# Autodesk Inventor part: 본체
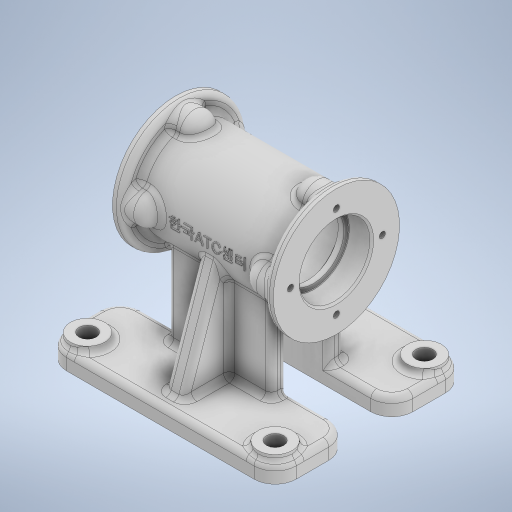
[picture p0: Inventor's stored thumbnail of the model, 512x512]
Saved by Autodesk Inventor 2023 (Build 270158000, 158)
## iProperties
Created: 2026-06
Part Number: 본체
Material: 일반
Document SubType Name: Modeling
Designer: 4강의실
Density: 1 g/cm^3
Appearance: 기본값
Author: 4강의실
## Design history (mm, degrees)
sketch "스케치1"
  geometry: L1 (-42, 0)-(-42, 33); L2 (-42, 33)-(-37, 33); L3 (-37, 33)-(-37, 25); L4 (-37, 25)-(37, 25); L5 (37, 25)-(37, 33); L6 (37, 33)-(42, 33); L7 (42, 33)-(42, 0); L8 (42, 0)-(-42, 0); 2 further points
  constraints: 16 end point, 5 perpendicular, 2 point on line, 1 coincident, 1 collinear, 1 horizontal, 1 midpoint, 1 vertical
  dimensions: "d0" = 84 distance between parallel lines of L7 L1; "d1" = 66 diameter of L2 L8; "d2" = 50 diameter of L4 L8; "d3" = 5 distance of L5.end L6.end
revolve "회전1" sketch "스케치1" stored, may be unused: angle "d4" = 90 deg
sketch "스케치3"
  geometry: L1 (-61, -50)-(-70, -50); L2 (-70, -50)-(-70, -11); L3 (-70, -11)-(-61, -11); L4 (-61, -11)-(-61, -50); L5 (0, 0)-(-63.878, 0); L6 (-61, -11)-(-22.45, -11); L7 (-16.248, -19)-(-61, -19); C1 r 33 at (0, 0) reference; A1 r 25 centre (0, 0) between (-22.45, -11) and (-16.248, -19) reference
  constraints: 14 end point, 3 horizontal, 2 parallel, 2 perpendicular, 2 point on circle, 1 point on line
  dimensions: "d12" = 70 distance from line of L2 L5.start; "d13" = 9 distance of L2.end L3.end; "d14" = 39 distance of L1.end L2.end; "d15" = 100 diameter of L1 L5; "d19" = 8 distance between parallel lines of L6 L7
extrude "돌출1" join sketch "스케치3" stored distance "d17" = 120; taper "d18" = 0 deg
extrude "돌출2" join sketch "스케치3" stored distance "d20" = 54; taper "d21" = 0 deg
sketch "스케치4"
  geometry: L1 (-6.346, -24.181)-(-61, -43); L2 (-61, -50)-(-61, -11) reference; L3 (-61, -19)-(-16.248, -19) reference; L4 (-70, -50)-(-61, -50) reference; A1 r 25 centre (0, 0) between (-6.346, -24.181) and (-16.248, -19) reference; 1 further point
  constraints: 2 end point, 1 point on circle, 1 point on line
  dimensions: "d22" = 19 deg angle of L3 L1; "d23" = 7 distance from line of L1.end L4
feature "리브1" sketch "스케치4" dims "d24" = 1, "d25" = 10, "d26" = 0, "d27" = 0, "d28" = 1, "d29" = 1
sketch "스케치5"
  geometry: L1 (0, 0)-(120, 0) reference; L2 (60, 0)-(60, 15.652); L3 (18, -17)-(18, -83) reference; L4 (18, -50)-(3.294, -50); C1 r 9 at (109, -11); C2 r 9 at (11, -11); 1 further point
  constraints: 4 end point, 2 centre point, 2 midpoint, 1 horizontal, 1 symmetric about line, 1 vertical, 1 other
  dimensions: "d30" = 18 diameter of C1; "d31" = 98 diameter of C1.centre L2; "d32" = 78 diameter of C1.centre L4
extrude "돌출3" join sketch "스케치5" distance "d33" = 3; taper "d34" = 0 deg
fillet "모깎기3" dims "d75" = 3
sketch "스케치6"
  geometry: L1 (42, 33)-(42, -33) reference; L2 (32, 32)-(37, 32); L3 (37, 33)-(37, -33) reference; L4 (32, 24)-(24, 24); L5 (37, 25)-(37, -25) reference; L6 (37, 32)-(37, 25); L7 (37, 25)-(24.063, 25); L8 (37, 25)-(-37, 25) reference; A1 r 8 centre (32, 24) between (37, 30.245) and (37, 17.755); A2 r 8 centre (32, 24) between (37, 17.755) and (37, 30.245); 1 further point
  constraints: 8 end point, 7 point on circle, 4 point on line, 2 centre point, 1 horizontal, 1 tangent
  dimensions: "d35" = 16 diameter of A1; "d36" = 24 vertical distance of point (0, 0) L4.start; "d37" = 10 distance from line of L1 L4.start
revolve "회전3" sketch "스케치6" stored, may be unused: angle "d38" = 90 deg
sketch "스케치8"
  geometry: 6 further points
  constraints: 2 vertical alignment, 1 coincident, 7 other
  dimensions: "d48" = 24 distance of point (0, 24) point (0, 0); "d51" = 360 deg dimension on point (0, 0) point (0, 24) (derived)
hole "구멍1" sketch "스케치8" at (0, 24), (-24, 0), (0, -24), (24, 0) diameter "d53" = 3.242; stored, may be unused: countersink angle "d57" = 90 deg, drill point angle "d59" = 118 deg; dims "d54" = 8, "d55" = 4, "d56" = 2, "d58" = 10
sketch "스케치7"
  geometry: L1 (42, 33)-(42, -33) reference; L2 (42, 0)-(30, 0); L3 (30, 0)-(30, 18.5); L4 (30, 18.5)-(42, 18.5); L5 (42, 18.5)-(42, 0); L6 (30, 0)-(27, 0); L7 (27, 0)-(27, 16); L8 (27, 16)-(30, 16); L9 (30, 16)-(30, 0); L10 (27, 0)-(-27, 0); L11 (-27, 0)-(-27, 20); L12 (-27, 20)-(27, 20); L13 (27, 20)-(27, 0); L14 (-27, 0)-(-30, 0); L15 (-30, 0)-(-30, 16); L16 (-30, 16)-(-27, 16); L17 (-27, 16)-(-27, 0); L18 (-42, 33)-(-42, -33) reference; L19 (-30, 0)-(-42, 0); L20 (-42, 0)-(-42, 18.5); L21 (-42, 18.5)-(-30, 18.5); L22 (-30, 18.5)-(-30, 0); 7 further points
  constraints: 40 end point, 10 parallel, 5 horizontal, 5 perpendicular, 3 point on line, 2 collinear, 1 midpoint
  dimensions: "d42" = 37 diameter of L4 L2; "d43" = 12 distance between parallel lines of L3 L5; "d44" = 54 distance of L11.end L12.end; "d45" = 40 diameter of L12 L10; "d46" = 32 diameter of L8 L6
revolve "회전4" sketch "스케치7" stored, may be unused: angle "d47" = 90 deg
sketch "스케치9"
  geometry: C1 r 9 at (0, 0) reference; C2 r 9 at (-98, 0) reference; C3 r 9 at (-98, -78) reference; C4 r 9 at (0, -78) reference; 5 further points
  constraints: 4 coincident
hole "구멍2" sketch "스케치9" at (0, 0), (-98, 0), (-98, -78), (0, -78) diameter "d60" = 9; stored, may be unused: countersink angle "d64" = 90 deg, drill point angle "d66" = 118 deg; dims "d61" = 8, "d62" = 4, "d63" = 2, "d65" = 10
chamfer "모따기1" distance "d67" = 1; stored, may be unused: second distance "d68" = 2, angle "d69" = 45 deg
fillet "모깎기6" dims "d78" = 11
fillet "모깎기1" dims "d73" = 0.3
fillet "모깎기2" dims "d74" = 3
fillet "모깎기4" dims "d76" = 3
fillet "모깎기5" dims "d77" = 3
fillet "모깎기7" dims "d79" = 3
fillet "모깎기8" dims "d80" = 3
fillet "모깎기9" dims "d81" = 3
node "작업 평면1"
sketch "스케치10"
  geometry: L1 (-49, -70)-(49, -70) reference; 2 further points
  constraints: 1 coincident, 1 other
  dimensions: "d83" = 70 distance from line of L1 point (0, 0)
feature "엠보싱1" sketch "스케치10" dims "d84" = 0.5, "d85" = 0
node "솔리드1"
pattern_circular "원형 패턴1" dims angle "d40" = 360 deg
mirror "미러1"
mirror "미러2"
mirror "미러3"
feature "A9D066F2-1C7D-4E18-AEED-F7BC21143FA4" dims "d60" = 9, "d61" = 8, "d62" = 4, "d63" = 2, "d64" = 90 deg, "d65" = 10, "d66" = 118 deg
other parameters: "d82" = 85.25
